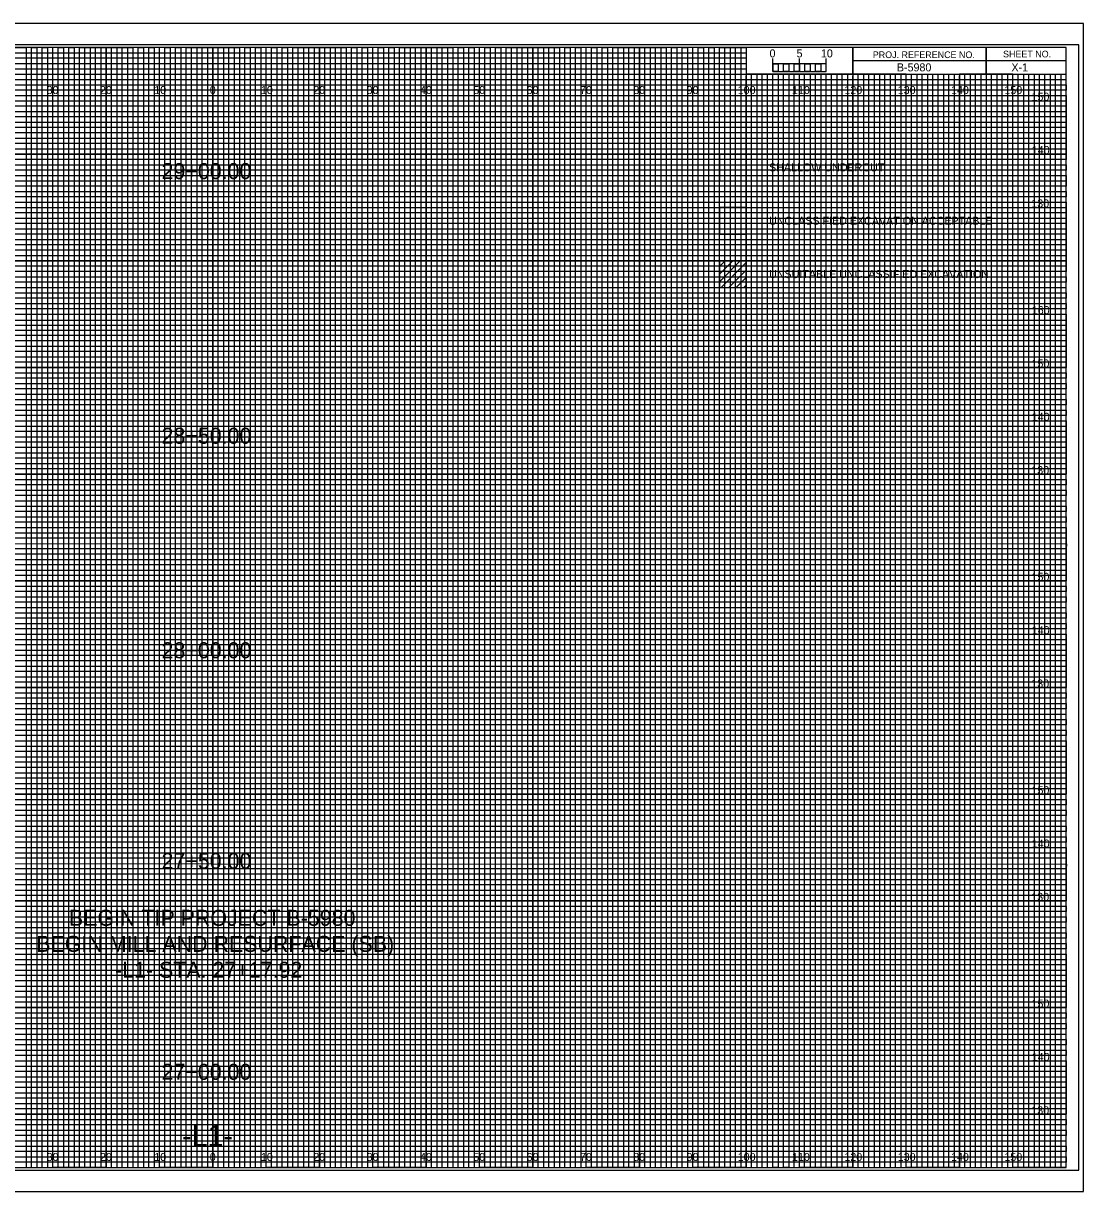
# Model space of a CAD drawing. Extents: x -13 to 323, y -5 to 3294.
# Drawn here: x 124.5 to 323.3, y -4.5 to 214.5 of the extents above; entities that cross this region are included whole.
import ezdxf

# ---------------------------------------------------------------- set-up
doc = ezdxf.new("R2010")
doc.units = 0
for name, color, linetype in [('Prop Road Sect_ Recs - UC Shallow (Outline)', 7, 'Continuous'), ('Prop Road Sect_ Recs - UC Shallow (Pattern)', 7, 'Continuous'), ('Prop Road Sect_ Recs - UEA (outline)', 7, 'Continuous'), ('Prop Road Sect_ Recs - UUC (Outline)', 7, 'Continuous'), ('Prop Road Sect_ Recs - UUC (pattern)', 7, 'Continuous'), ('Prop XS Alignment Label', 7, 'Continuous'), ('Prop XS Bar Scale Labels', 7, 'Continuous'), ('Prop XS Elevation Labels', 7, 'Continuous'), ('Prop XS Offset Labels', 7, 'Continuous'), ('Prop XS Project Number', 7, 'Continuous'), ('Prop XS Sheet Number', 7, 'Continuous'), ('Prop XS Station Labels', 7, 'Continuous'), ('Sheet Cross Section CELL', 7, 'Continuous'), ('Sheet Cross Section Grid Major CELL', 7, 'Continuous'), ('Sheet Cross Section Grid Middle CELL', 7, 'Continuous'), ('Sheet Cross Section Grid Minor 1 CELL', 7, 'Continuous'), ('Sheet Cross Section Grid Minor 2 CELL', 7, 'Continuous'), ('Sheet Cross Section Scale CELL', 7, 'Continuous'), ('Sheet Cutting Line CELL', 7, 'Continuous'), ('Sheet DOT Grid CELL', 7, 'Continuous'), ('Sheet Plot Border Inside CELL', 7, 'Continuous'), ('Sheet Plot Border Outside CELL', 7, 'Continuous')]:
    doc.layers.add(name, color=color, linetype=linetype)

msp = doc.modelspace()

# ---------------------------------------------------------------- linework, layer by layer
at = {"layer": 'Prop Road Sect_ Recs - UC Shallow (Outline)'}
msp.add_lwpolyline([(255, 190), (255, 185), (260, 185), (260, 185), (260, 190), (260, 190)], close=True, dxfattribs=at)
at = {"layer": 'Prop Road Sect_ Recs - UC Shallow (Pattern)'}
msp.add_lwpolyline([(255, 190), (255, 185), (260, 185), (260, 190), (255, 190)], dxfattribs=at)
at = {"layer": 'Prop Road Sect_ Recs - UEA (outline)'}
msp.add_lwpolyline([(255, 180), (255, 175), (260, 175), (260, 180)], close=True, dxfattribs=at)
at = {"layer": 'Prop Road Sect_ Recs - UUC (Outline)'}
msp.add_lwpolyline([(255, 170), (255, 165), (260, 165), (260, 170)], close=True, dxfattribs=at)
at = {"layer": 'Prop Road Sect_ Recs - UUC (pattern)'}
for p, q in [((255, 166.07), (258.93, 170)), ((255, 167.48), (257.52, 170)), ((255, 168.9), (256.1, 170)), ((255.34, 165), (260, 169.66)), ((256.76, 165), (260, 168.24)), ((258.17, 165), (260, 166.83)), ((259.59, 165), (260, 165.41))]:
    msp.add_line(p, q, dxfattribs=at)
at = {"layer": 'Sheet Cross Section CELL'}
for p, q in [((305, 210), (305, 205)), ((305, 205), (305, 210)), ((280, 207.5), (280, 205)), ((320, 207.49), (280, 207.49)), ((280, 205), (320, 205))]:
    msp.add_line(p, q, dxfattribs=at)
for points in [[(320, 210), (0, 210), (0, 0), (320, 0)], [(280, 210), (260, 210), (260, 205.03), (280, 205.03)], [(320, 210), (280, 210), (280, 205), (320, 205)]]:
    msp.add_lwpolyline(points, close=True, dxfattribs=at)
at = {"layer": 'Sheet Cross Section Grid Major CELL'}
for p, q in [((130, 210), (120, 210)), ((130, 0), (130, 210)), ((150, 210), (140, 210)), ((140, 210), (140, 0)), ((150, 0), (150, 210)), ((170, 210), (160, 210)), ((160, 210), (160, 0)), ((170, 0), (170, 210)), ((190, 210), (180, 210)), ((180, 210), (180, 0)), ((190, 0), (190, 210)), ((210, 210), (200, 210)), ((200, 210), (200, 0)), ((210, 0), (210, 210)), ((230, 210), (220, 210)), ((220, 210), (220, 0)), ((230, 0), (230, 210)), ((250, 210), (240, 210)), ((240, 210), (240, 0)), ((250, 0), (250, 210)), ((260, 210), (260, 0)), ((270, 0), (270, 205)), ((290, 205), (280, 205)), ((280, 205), (280, 0)), ((290, 0), (290, 205)), ((310, 205), (300, 205)), ((300, 205), (300, 0)), ((310, 0), (310, 205)), ((140, 0), (130, 0)), ((160, 0), (150, 0)), ((180, 0), (170, 0)), ((200, 0), (190, 0)), ((220, 0), (210, 0)), ((240, 0), (230, 0)), ((260, 0), (250, 0)), ((280, 0), (270, 0)), ((300, 0), (290, 0)), ((320, 0), (310, 0)), ((320, 0), (320, 0))]:
    msp.add_line(p, q, dxfattribs=at)
for points in [[(0, 200), (320, 200), (320, 190), (0, 190)], [(0, 180), (320, 180), (320, 170), (0, 170)], [(0, 160), (320, 160), (320, 150), (0, 150)], [(0, 140), (320, 140), (320, 130), (0, 130)], [(0, 120), (320, 120), (320, 110), (0, 110)], [(0, 100), (320, 100), (320, 90), (0, 90)], [(0, 80), (320, 80), (320, 70), (0, 70)], [(0, 60), (320, 60), (320, 50), (0, 50)], [(0, 40), (320, 40), (320, 30), (0, 30)], [(0, 20), (320, 20), (320, 10), (0, 10)]]:
    msp.add_lwpolyline(points, dxfattribs=at)
at = {"layer": 'Sheet Cross Section Grid Middle CELL'}
for points in [[(115, 210), (125, 210), (125, 0), (135, 0), (135, 210), (145, 210), (145, 0), (155, 0), (155, 210), (165, 210), (165, 0), (175, 0), (175, 210), (185, 210), (185, 0), (195, 0), (195, 210), (205, 210), (205, 0), (215, 0), (215, 210), (225, 210), (225, 0), (235, 0), (235, 210), (245, 210), (245, 0), (255, 0), (255, 210), (259.93, 210), (260, 210), (260, 205), (264.99, 205), (264.99, 0), (275, 0), (275, 205), (285, 205), (285, 0), (295, 0), (295, 205), (305, 205), (305, 0), (315, 0), (315, 205)], [(0, 205), (275, 205)], [(0, 185), (320, 185), (320, 195), (0, 195)], [(0, 165), (320, 165), (320, 175), (0, 175)], [(0, 145), (320, 145), (320, 155), (0, 155)], [(0, 125), (320, 125), (320, 135), (0, 135)], [(0, 105), (320, 105), (320, 115), (0, 115)], [(0, 85), (320, 85), (320, 95), (0, 95)], [(0, 65), (320, 65), (320, 75), (0, 75)], [(0, 45), (320, 45), (320, 55), (0, 55)], [(0, 25), (320, 25), (320, 35), (0, 35)], [(0, 5), (320, 5), (320, 15), (0, 15)]]:
    msp.add_lwpolyline(points, dxfattribs=at)
at = {"layer": 'Sheet Cross Section Grid Minor 1 CELL'}
for p, q in [((0, 209), (260, 209)), ((260, 209), (260, 207.98)), ((260, 207.98), (0, 207.98)), ((0, 207), (260, 207)), ((260, 205.89), (0, 205.89)), ((260, 207), (260, 205.89)), ((0, 204), (320, 204))]:
    msp.add_line(p, q, dxfattribs=at)
for points in [[(0, 203), (270, 203), (320, 203), (320, 202), (0, 202)], [(0, 201), (320, 201), (320, 199), (0, 199)], [(0, 198), (320, 198), (320, 197), (0, 196.98)], [(0, 196), (320, 196), (320, 194), (0, 194)], [(0, 193), (320, 193), (320, 192), (0, 192)], [(0, 191), (320, 191), (320, 189), (0, 189)], [(0, 188), (320, 188), (320, 187), (0, 187)], [(0, 186), (320, 186), (320, 184), (0, 184)], [(0, 183), (320, 183), (320, 182), (0, 182)], [(0, 181), (320, 181), (320, 179), (0, 179)], [(0, 178), (320, 178), (320, 177), (0, 177)], [(0, 176), (320, 176), (320, 173.95), (320, 173), (320, 172), (0, 172)], [(0, 174), (320, 174), (320, 173), (0, 173)], [(0, 171), (320, 171), (320, 169), (0, 169.03)], [(0, 169.03), (320, 169), (320, 168), (0, 168)], [(0, 167), (320, 167), (320, 166), (0, 166)], [(0, 164), (320, 164), (320, 163), (0, 163)], [(0, 162), (320, 162), (320, 161), (0, 161)], [(-0.07, 158.89), (320, 158.89), (320, 157.88), (-0.07, 157.88)], [(0, 157), (320, 157), (320, 156), (0, 156)], [(0, 154), (320, 154), (320, 153), (0, 153)], [(0, 152), (320, 152), (320, 151), (0, 151)], [(0, 149), (320, 149), (320, 148), (0, 148)], [(0, 147), (320, 147), (320, 146), (0, 146)], [(0, 144), (320, 144), (320, 143), (0, 143)], [(0, 142), (320, 142), (320, 141), (0, 141)], [(0, 139), (320, 139), (319.99, 137.98), (0, 138)], [(0, 137), (320, 137), (320, 136), (0, 136)], [(0, 134), (320, 134), (320, 133), (0, 133)], [(0, 132), (320, 132), (320, 131), (0, 131)], [(0, 129), (320, 129), (320, 128), (0, 128)], [(0, 127), (320, 127), (320, 126), (0, 126)], [(0, 124), (320, 124), (320, 123), (0, 123)], [(0, 122), (320, 122), (320, 121), (0, 121)], [(0, 119), (320, 119), (320, 118), (0, 118)], [(0, 116.99), (320.07, 116.91), (320, 116), (0, 116)], [(0, 114), (320, 114), (320, 113), (0, 113)], [(0, 112), (320, 112), (320, 111), (0, 111)], [(0, 109), (320, 109), (320, 108), (0, 108)], [(0, 107), (320, 107), (320, 106), (0, 106)], [(0, 104), (320, 104), (320, 103), (0, 103)], [(0, 102), (320, 102), (320, 101), (0, 101)], [(0, 99), (320, 99), (320, 98), (0, 98)], [(0, 97), (320, 97), (320, 96), (0, 96)], [(0, 94), (320, 94), (320, 93), (0, 93)], [(0, 92), (320, 92), (320, 91), (0, 91)], [(0, 89), (320, 89), (320, 88), (0, 88)], [(0, 87), (320, 87), (320, 86), (0, 86)], [(0, 84), (320, 84), (320, 83), (0, 83)], [(0, 82), (320, 82), (320, 81), (0, 81)], [(0, 79), (320, 79), (319.99, 77.98), (0, 78)], [(0, 77), (320, 77), (320, 76), (0, 76)], [(0, 74), (320, 74), (320, 73), (0, 73)], [(0, 72), (320, 72), (320, 71), (0, 71)], [(0, 69), (320, 69), (320, 68), (0, 68)], [(0, 67), (320, 67), (320, 66), (0, 66)], [(0, 64), (320, 64), (320, 63), (0, 63)], [(0, 62), (320, 62), (320, 61), (0, 61)], [(0, 59), (320, 59), (320, 58), (0, 58)], [(0, 56.99), (320.07, 56.91), (320, 56), (0, 56)], [(0, 54), (320, 54), (320, 53), (0, 53)], [(0, 52), (320, 52), (320, 51), (0, 51)], [(0, 49), (320, 49), (320, 48), (0, 48)], [(0, 47), (320, 47), (320, 46), (0, 46)], [(0, 44), (320, 44), (320, 43), (0, 43)], [(0, 42), (320, 42), (320, 41), (0, 41)], [(0, 39), (320, 39), (320, 38), (0, 38)], [(0, 37), (320, 37), (320, 36), (0, 36)], [(0, 34), (320, 34), (320, 33), (0, 33)], [(0, 32), (320, 32), (320, 31), (0, 31)], [(0, 29), (320, 29), (320, 28), (0, 28)], [(0, 27), (320, 27), (320, 26), (0, 26)], [(0, 24), (320, 24), (320, 23), (0, 23)], [(0, 22), (320, 22), (320, 21), (0, 21)], [(0, 19), (320, 19), (320, 18), (0, 18)], [(0, 17), (320, 17), (320, 16), (0, 16)], [(0, 14), (320, 14), (320, 13), (0, 13)], [(0, 12), (320, 12), (320, 11), (0, 11)], [(0, 9), (320, 9), (320, 8), (0, 8)], [(0, 7), (320, 7), (320, 6), (0, 6)], [(0, 4), (320, 4), (320, 3), (0, 3)], [(0, 2), (320, 2), (320, 1), (0, 1)]]:
    msp.add_lwpolyline(points, dxfattribs=at)
at = {"layer": 'Sheet Cross Section Grid Minor 2 CELL'}
for p, q in [((267, 205), (266.01, 205)), ((266.01, 205), (266.01, 0)), ((267, 0), (267, 205)), ((269, 205), (268, 205)), ((268, 205), (268, 0)), ((269, 0), (269, 205)), ((266.01, 0), (265, 0)), ((268, 0), (267, 0))]:
    msp.add_line(p, q, dxfattribs=at)
for points in [[(125, 0), (126, 0), (126, 210), (127, 210), (127, 0)], [(127, 0), (128, 0), (128, 210), (129, 210), (129, 0)], [(130, 0), (131, 0), (131, 210), (132, 210), (132, 0)], [(132, 0), (133, 0), (133, 210), (134, 210), (134, 0)], [(135, 0), (136, 0), (136, 210), (137, 210), (137, 0)], [(137, 0), (138, 0), (138, 210), (139, 210), (139, 0)], [(140, 0), (141, 0), (141, 210), (142, 210), (142, 0)], [(142, 0), (143, 0), (143, 210), (144, 210), (144, 0)], [(145, 0), (146, 0), (146, 210), (147, 210), (147, 0)], [(147, 0), (148, 0), (148, 210), (149, 210), (149, 0)], [(150, 0), (151, 0), (151, 210), (152, 210), (152, 0)], [(152, 0), (153, 0), (153, 210), (154, 210), (154, 0)], [(155, 0), (156, 0), (156, 210), (157, 210), (157, 0)], [(157, 0), (158, 0), (158, 210), (159, 210), (159, 0)], [(160, 0), (161, 0), (161, 210), (162, 210), (162, 0)], [(162, 0), (163, 0), (163, 210), (164, 210), (164, 0)], [(165, 0), (166, 0), (166, 210), (167, 210), (167, 0)], [(167, 0), (168, 0), (168, 210), (169, 210), (169, 0)], [(170, 0), (171, 0), (171, 210), (172, 210), (172, 0)], [(172, 0), (173, 0), (173, 210), (174, 210), (174, 0)], [(175, 0), (176, 0), (176, 210), (177, 210), (177, 0)], [(177, 0), (178, 0), (178, 210), (179, 210), (179, 0)], [(180, 0), (181, 0), (181, 210), (182, 210), (182, 0)], [(182, 0), (183, 0), (183, 210), (184, 210), (184, 0)], [(185, 0), (186, 0), (186, 210), (187, 210), (187, 0)], [(187, 0), (188, 0), (188, 210), (189, 210), (189, 0)], [(190, 0), (191, 0), (191, 210), (192, 210), (192, 0)], [(192, 0), (193, 0), (193, 210), (194, 210), (194, 0)], [(195, 0), (196, 0), (196, 210), (197, 210), (197, 0)], [(197, 0), (198, 0), (198, 210), (199, 210), (199, 0)], [(200, 0), (201, 0), (201, 210), (202, 210), (202, 0)], [(202, 0), (203, 0), (203, 210), (204, 210), (204, 0)], [(205, 0), (206, 0), (206, 210), (207, 210), (207, 0)], [(207, 0), (208, 0), (208, 210), (209, 210), (209, 0)], [(210, 0), (211, 0), (211, 210), (212, 210), (212, 0)], [(212, 0), (213, 0), (213, 210), (214, 210), (214, 0)], [(215, 0), (216, 0), (216, 210), (217, 210), (217, 0)], [(217, 0), (218, 0), (218, 210), (219, 210), (219, 0)], [(220, 0), (221, 0), (221, 210), (222, 210), (222, 0)], [(222, 0), (223, 0), (223, 210), (224, 210), (224, 0)], [(225, 0), (226, 0), (226, 210), (227, 210), (227, 0)], [(227, 0), (228, 0), (228, 210), (229, 210), (229, 0)], [(230, 0), (231, 0), (231, 210), (232, 210), (232, 0)], [(232, 0), (233, 0), (233, 210), (234, 210), (234, 0)], [(235, 0), (236, 0), (236, 210), (237, 210), (237, 0)], [(237, 0), (238, 0), (238, 210), (239, 210), (239, 0)], [(240, 0), (241, 0), (241, 210), (242, 210), (242, 0)], [(242, 0), (243, 0), (243, 210), (244, 210), (244, 0)], [(245, 0), (246, 0), (246, 210), (247, 210), (247, 0)], [(247, 0), (248, 0), (248, 210), (249, 210), (249, 0)], [(250, 0), (251, 0), (251, 210), (252, 210), (252, 0)], [(252, 0), (253, 0), (253, 210), (254, 210), (254, 0)], [(255, 0), (256, 0), (256, 210), (257, 210), (257, 0)], [(257, 0), (258, 0), (258, 210), (259, 210), (259, 0)], [(260, 0), (261, 0), (261, 205), (262.02, 205), (262.02, 0)], [(262, 0), (263, 0), (263, 205), (263.99, 205), (263.99, 0)], [(270, 0), (270.98, 0), (270.98, 205), (272, 205), (272, 0)], [(272, 0), (273, 0), (273, 205), (274.05, 205), (274.05, 0)], [(275, 0), (276, 0), (276, 205), (277, 205), (277, 0)], [(277, 0), (278, 0), (278, 205), (279, 205), (279, 0)], [(280, 0), (281, 0), (281, 205), (282, 205), (282, 0)], [(282, 0), (283, 0), (283, 205), (284, 205), (284, 0)], [(285, 0), (286, 0), (286, 205), (287, 205), (287, 0)], [(287, 0), (288, 0), (288, 205), (289, 205), (289, 0)], [(290, 0), (291, 0), (291, 205), (292, 205), (292, 0)], [(292, 0), (293, 0), (293, 205), (294, 205), (294, 0)], [(295, 0), (296, 0), (296, 205), (297, 205), (297, 0)], [(297, 0), (298, 0), (298, 205), (299, 205), (299, 0)], [(300, 0), (301, 0), (301, 205), (302, 205), (302, 0)], [(302, 0), (303, 0), (303, 205), (304, 205), (304, 0)], [(305, 0), (306, 0), (306, 205), (307, 205), (307, 0)], [(307, 0), (308, 0), (308, 205), (309, 205), (309, 0)], [(310, 0), (311, 0), (311, 205), (312, 205), (312, 0)], [(312, 0), (313, 0), (313, 205), (314, 205), (314, 0)], [(315, 0), (316, 0), (316, 205), (317, 205), (317, 0)], [(317, 0), (318, 0), (318, 205), (319, 205), (319, 0)]]:
    msp.add_lwpolyline(points, dxfattribs=at)
at = {"layer": 'Sheet Cross Section Scale CELL'}
for p, q in [((265, 205.49), (265, 207.9)), ((265, 206.9), (265, 207.9)), ((270, 205.49), (270, 207.9)), ((275, 205.49), (275, 207.9)), ((275, 206.9), (275, 207.9))]:
    msp.add_line(p, q, dxfattribs=at)
for points in [[(275, 206.9), (265, 206.9), (265, 205.49), (275, 205.49)], [(265, 206.9), (266, 206.9), (266, 205.49), (265, 205.49)], [(267, 206.9), (268, 206.9), (268, 205.49), (267, 205.49)], [(269, 206.9), (270, 206.9), (270, 205.49), (269, 205.49)], [(271, 206.9), (272, 206.9), (272, 205.49), (271, 205.49)], [(273, 206.9), (274, 206.9), (274, 205.49), (273, 205.49)]]:
    msp.add_lwpolyline(points, close=True, dxfattribs=at)
at = {"layer": 'Sheet Cutting Line CELL'}
for p, q in [((323.3, 214.5), (-13.4, 214.5)), ((-13.4, -4.5), (323.3, -4.5))]:
    msp.add_line(p, q, dxfattribs=at)
at = {"layer": 'Sheet DOT Grid CELL'}
for p, q in [((130, 0), (130, 210)), ((140, 0), (140, 210)), ((150, 0), (150, 210)), ((160, 0), (160, 210)), ((170, 0), (170, 210)), ((180, 0), (180, 210)), ((190, 0), (190, 210)), ((200, 0), (200, 210)), ((210, 0), (210, 210)), ((220, 0), (220, 210)), ((230, 0), (230, 210)), ((240, 0), (240, 210)), ((250, 0), (250, 210)), ((260, 0), (260, 204.69)), ((270, 0), (270, 204.69)), ((280, 0), (280, 204.69)), ((290, 0), (290, 204.69)), ((300, 0), (300, 204.69)), ((310, 0), (310, 204.69)), ((0, 200), (320, 200)), ((0, 190), (320, 190)), ((0, 180), (320, 180)), ((0, 170), (320, 170)), ((0, 160), (320, 160)), ((0, 150), (320, 150)), ((0, 140), (320, 140)), ((0, 130), (320, 130)), ((0, 120), (320, 120)), ((0, 110), (320, 110)), ((0, 100), (320, 100)), ((0, 90), (320, 90)), ((0, 80), (320, 80)), ((0, 70), (320, 70)), ((0, 60), (320, 60)), ((0, 50), (320, 50)), ((0, 40), (320, 40)), ((0, 30), (320, 30)), ((0, 20), (320, 20)), ((0, 10), (320, 10))]:
    msp.add_line(p, q, dxfattribs=at)
at = {"layer": 'Sheet Plot Border Inside CELL'}
msp.add_lwpolyline([(-10.8, -0.5), (322.4, -0.5), (322.4, 210.5), (-10.8, 210.5)], close=True, dxfattribs=at)
at = {"layer": 'Sheet Plot Border Outside CELL'}
msp.add_lwpolyline([(-13.4, -4.5), (323.3, -4.5), (323.3, 214.5), (-13.4, 214.5)], close=True, dxfattribs=at)

# ---------------------------------------------------------------- texts
at = {"layer": 'Prop XS Alignment Label'}
msp.add_text('-L1-', height=4, dxfattribs=at).set_placement((154.28, 4))
at = {"layer": 'Prop XS Bar Scale Labels'}
for s, p in [('5', (269.47, 208.12)), ('10', (274.04, 208.12))]:
    msp.add_text(s, height=1.5, dxfattribs=at).set_placement(p)
at = {"layer": 'Prop XS Elevation Labels'}
for s, p in [('150', (313.52, 200)), ('140', (313.57, 190)), ('130', (313.49, 180)), ('160', (313.57, 160)), ('150', (313.52, 150)), ('140', (313.57, 140)), ('130', (313.49, 130)), ('150', (313.52, 110)), ('140', (313.57, 100)), ('130', (313.49, 90)), ('150', (313.52, 70)), ('140', (313.57, 60)), ('130', (313.49, 50)), ('150', (313.52, 30)), ('140', (313.57, 20)), ('130', (313.49, 10))]:
    msp.add_text(s, height=1.5, dxfattribs=at).set_placement(p)
at = {"layer": 'Prop XS Offset Labels'}
for s, p in [('30', (128.86, 201.25)), ('20', (138.86, 201.25)), ('10', (149.04, 201.25)), ('0', (159.45, 201.25)), ('0', (159.45, 201.25)), ('10', (169.04, 201.25)), ('20', (178.86, 201.25)), ('30', (188.86, 201.25)), ('40', (198.86, 201.25)), ('50', (208.86, 201.25)), ('60', (218.86, 201.25)), ('70', (228.86, 201.25)), ('80', (238.86, 201.25)), ('90', (248.86, 201.25)), ('100', (258.44, 201.25)), ('110', (268.62, 201.25)), ('120', (278.44, 201.25)), ('130', (288.44, 201.25)), ('140', (298.44, 201.25)), ('150', (308.44, 201.25)), ('30', (128.86, 1.25)), ('20', (138.86, 1.25)), ('10', (149.04, 1.25)), ('0', (159.45, 1.25)), ('0', (159.45, 1.25)), ('10', (169.04, 1.25)), ('20', (178.86, 1.25)), ('30', (188.86, 1.25)), ('40', (198.86, 1.25)), ('50', (208.86, 1.25)), ('60', (218.86, 1.25)), ('70', (228.86, 1.25)), ('80', (238.86, 1.25)), ('90', (248.86, 1.25)), ('100', (258.44, 1.25)), ('110', (268.62, 1.25)), ('120', (278.44, 1.25)), ('130', (288.44, 1.25)), ('140', (298.44, 1.25)), ('150', (308.44, 1.25))]:
    msp.add_text(s, height=1.5, dxfattribs=at).set_placement(p)
at = {"layer": 'Prop XS Project Number'}
msp.add_text('B-5980', height=1.5, dxfattribs=at).set_placement((288.28, 205.5))
at = {"layer": 'Prop XS Sheet Number'}
msp.add_text('X-1', height=1.5, dxfattribs=at).set_placement((309.76, 205.5))
at = {"layer": 'Prop XS Station Labels'}
for s, height, p in [('29+00.00', 3, (150.41, 185.31)), ('SHALLOW UNDERCUT', 1.5, (264.31, 186.75)), ('UNCLASSIFIED EXCAVATION ACCEPTABLE', 1.5, (264.31, 176.75)), ('UNSUITABLE UNCLASSIFIED EXCAVATION', 1.5, (264.31, 166.75)), ('28+50.00', 3, (150.41, 135.7)), ('28+00.00', 3, (150.41, 95.48)), ('27+50.00', 3, (150.41, 56)), ('BEGIN TIP PROJECT B-5980', 3, (133.04, 45.33)), ('BEGIN MILL AND RESURFACE (SB)', 3, (126.93, 40.45)), ('-L1- STA. 27+17.92', 3, (141.68, 35.58)), ('27+00.00', 3, (150.41, 16.46))]:
    msp.add_text(s, height=height, dxfattribs=at).set_placement(p)
at = {"layer": 'Sheet Cross Section CELL'}
for s, p in [('PROJ. REFERENCE NO.', (283.77, 207.99)), ('SHEET NO.', (308.19, 208.12))]:
    msp.add_text(s, height=1.25, dxfattribs=at).set_placement(p)
at = {"layer": 'Sheet Cross Section Scale CELL'}
msp.add_text('0', height=1.5, dxfattribs=at).set_placement((264.41, 208.12))

doc.saveas('drawing.dxf')
